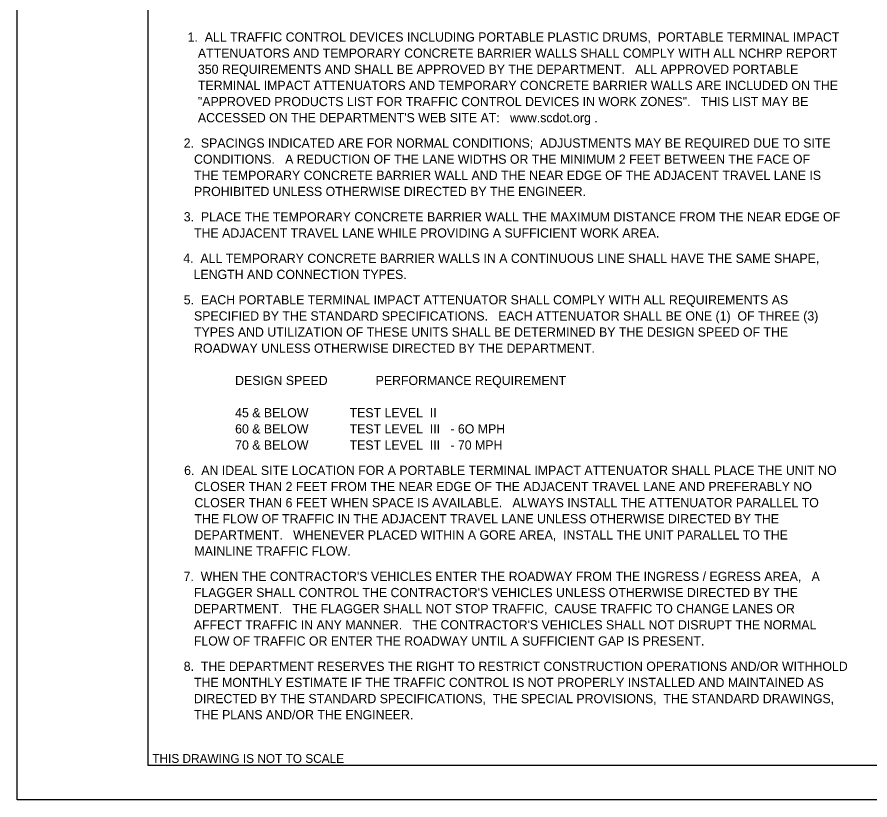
# Model space of a CAD drawing. Extents: x -2433 to -1135, y -5611 to -4633.
# Drawn here: x -2432.9 to -1989.1, y -5447.9 to -5040.4 of the extents above; entities that cross this region are included whole.
import ezdxf

# ---------------------------------------------------------------- set-up
doc = ezdxf.new("R2010")
doc.units = 0
doc.layers.add('Level 42', color=7, linetype='Continuous')
doc.layers.add('Level 50', color=7, linetype='Continuous')

msp = doc.modelspace()

# ---------------------------------------------------------------- linework, layer by layer
at = {"layer": 'Level 42'}
for p, q in [((-2364.77, -5429.98), (-2364.77, -4648.78)), ((-1170.64, -5429.98), (-2364.77, -5429.98))]:
    msp.add_line(p, q, dxfattribs=at)
msp.add_lwpolyline([(-2364.77, -4648.78), (-1304.73, -4648.78), (-1304.73, -5430.02), (-2364.77, -5430.02)], close=True, dxfattribs=at)
at = {"layer": 'Level 50'}
msp.add_lwpolyline([(-2432.94, -4632.82), (-1157.59, -4632.82), (-1157.59, -5447.91), (-2432.94, -5447.91)], close=True, dxfattribs=at)

# ---------------------------------------------------------------- texts
at = {"layer": 'Level 42'}
for s, height, p in [('1.  ALL TRAFFIC CONTROL DEVICES INCLUDING PORTABLE PLASTIC DRUMS,  PORTABLE TERMINAL IMPACT', 4.8, (-2344.17, -5053.14)), ('   ATTENUATORS AND TEMPORARY CONCRETE BARRIER WALLS SHALL COMPLY WITH ALL NCHRP REPORT', 4.8, (-2344.17, -5061.54)), ('   350 REQUIREMENTS AND SHALL BE APPROVED BY THE DEPARTMENT.   ALL APPROVED PORTABLE', 4.8, (-2344.17, -5069.94)), ('   TERMINAL IMPACT ATTENUATORS AND TEMPORARY CONCRETE BARRIER WALLS ARE INCLUDED ON THE ', 4.8, (-2344.17, -5078.34)), ('   "APPROVED PRODUCTS LIST FOR TRAFFIC CONTROL DEVICES IN WORK ZONES".   THIS LIST MAY BE', 4.8, (-2344.17, -5086.74)), ("   ACCESSED ON THE DEPARTMENT'S WEB SITE AT:   www.scdot.org .", 4.8, (-2344.17, -5095.14)), ('2.  SPACINGS INDICATED ARE FOR NORMAL CONDITIONS;  ADJUSTMENTS MAY BE REQUIRED DUE TO SITE', 4.8, (-2346.21, -5108.34)), ('   CONDITIONS.   A REDUCTION OF THE LANE WIDTHS OR THE MINIMUM 2 FEET BETWEEN THE FACE OF', 4.8, (-2346.21, -5116.74)), ('   THE TEMPORARY CONCRETE BARRIER WALL AND THE NEAR EDGE OF THE ADJACENT TRAVEL LANE IS', 4.8, (-2346.21, -5125.14)), ('   PROHIBITED UNLESS OTHERWISE DIRECTED BY THE ENGINEER.', 4.8, (-2346.21, -5133.54)), ('3.  PLACE THE TEMPORARY CONCRETE BARRIER WALL THE MAXIMUM DISTANCE FROM THE NEAR EDGE OF', 4.8, (-2346.21, -5146.74)), ('   THE ADJACENT TRAVEL LANE WHILE PROVIDING A SUFFICIENT WORK AREA.', 4.8, (-2346.21, -5155.14)), ('4.  ALL TEMPORARY CONCRETE BARRIER WALLS IN A CONTINUOUS LINE SHALL HAVE THE SAME SHAPE,', 4.8, (-2346.44, -5168.34)), ('   LENGTH AND CONNECTION TYPES.', 4.8, (-2346.44, -5176.74)), ('5.  EACH PORTABLE TERMINAL IMPACT ATTENUATOR SHALL COMPLY WITH ALL REQUIREMENTS AS ', 4.8, (-2346.21, -5189.94)), ('   SPECIFIED BY THE STANDARD SPECIFICATIONS.   EACH ATTENUATOR SHALL BE ONE (1)  OF THREE (3) ', 4.8, (-2346.21, -5198.34)), ('   TYPES AND UTILIZATION OF THESE UNITS SHALL BE DETERMINED BY THE DESIGN SPEED OF THE ', 4.8, (-2346.21, -5206.74)), ('   ROADWAY UNLESS OTHERWISE DIRECTED BY THE DEPARTMENT.', 4.8, (-2346.21, -5215.14)), ('               DESIGN SPEED              PERFORMANCE REQUIREMENT', 4.8, (-2346.21, -5231.94)), ('               45 & BELOW            TEST LEVEL  II', 4.8, (-2346.21, -5248.74)), ('               60 & BELOW            TEST LEVEL  III   - 6O MPH  ', 4.8, (-2346.21, -5257.14)), ('               70 & BELOW            TEST LEVEL  III   - 70 MPH', 4.8, (-2346.21, -5265.54)), ('6.  AN IDEAL SITE LOCATION FOR A PORTABLE TERMINAL IMPACT ATTENUATOR SHALL PLACE THE UNIT NO', 4.8, (-2345.99, -5278.74)), ('   CLOSER THAN 2 FEET FROM THE NEAR EDGE OF THE ADJACENT TRAVEL LANE AND PREFERABLY NO ', 4.8, (-2345.99, -5287.14)), ('   CLOSER THAN 6 FEET WHEN SPACE IS AVAILABLE.   ALWAYS INSTALL THE ATTENUATOR PARALLEL TO', 4.8, (-2345.99, -5295.54)), ('   THE FLOW OF TRAFFIC IN THE ADJACENT TRAVEL LANE UNLESS OTHERWISE DIRECTED BY THE ', 4.8, (-2345.99, -5303.94)), ('   DEPARTMENT.   WHENEVER PLACED WITHIN A GORE AREA,  INSTALL THE UNIT PARALLEL TO THE ', 4.8, (-2345.99, -5312.34)), ('   MAINLINE TRAFFIC FLOW.', 4.8, (-2345.99, -5320.74)), ("7.  WHEN THE CONTRACTOR'S VEHICLES ENTER THE ROADWAY FROM THE INGRESS / EGRESS AREA,   A", 4.8, (-2346.29, -5333.94)), ("   FLAGGER SHALL CONTROL THE CONTRACTOR'S VEHICLES UNLESS OTHERWISE DIRECTED BY THE", 4.8, (-2346.29, -5342.34)), ('   DEPARTMENT.   THE FLAGGER SHALL NOT STOP TRAFFIC,  CAUSE TRAFFIC TO CHANGE LANES OR ', 4.8, (-2346.29, -5350.74)), ("   AFFECT TRAFFIC IN ANY MANNER.   THE CONTRACTOR'S VEHICLES SHALL NOT DISRUPT THE NORMAL", 4.8, (-2346.29, -5359.14)), ('   FLOW OF TRAFFIC OR ENTER THE ROADWAY UNTIL A SUFFICIENT GAP IS PRESENT.', 4.8, (-2346.29, -5367.54)), ('8.  THE DEPARTMENT RESERVES THE RIGHT TO RESTRICT CONSTRUCTION OPERATIONS AND/OR WITHHOLD', 4.8, (-2346.21, -5380.74)), ('   THE MONTHLY ESTIMATE IF THE TRAFFIC CONTROL IS NOT PROPERLY INSTALLED AND MAINTAINED AS', 4.8, (-2346.21, -5389.14)), ('   DIRECTED BY THE STANDARD SPECIFICATIONS,  THE SPECIAL PROVISIONS,  THE STANDARD DRAWINGS,', 4.8, (-2346.21, -5397.54)), ('   THE PLANS AND/OR THE ENGINEER.', 4.8, (-2346.21, -5405.94)), ('THIS DRAWING IS NOT TO SCALE', 4.6, (-2362.56, -5428.61))]:
    msp.add_text(s, height=height, dxfattribs=at).set_placement(p)

doc.saveas('drawing.dxf')
